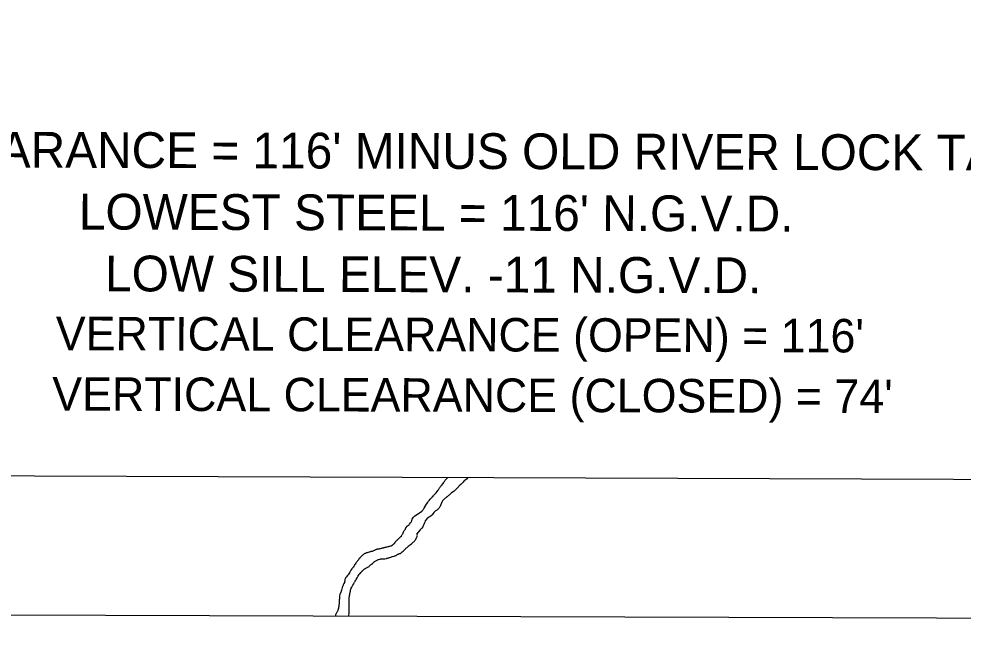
# Model space of a CAD drawing. Extents: x 3146026 to 3183936, y 897894 to 923344.
# Drawn here: x 3151849 to 3154671, y 903274 to 905151 of the extents above; entities that cross this region are included whole.
import ezdxf

# ---------------------------------------------------------------- set-up
doc = ezdxf.new("R2010")
doc.units = 0
for name, color, linetype in [('V-ANNO-SYMB', 7, 'Continuous'), ('V-GRID-FRAM', 7, 'Continuous'), ('V-TOPO-SHOR', 7, 'Continuous')]:
    doc.layers.add(name, color=color, linetype=linetype)

msp = doc.modelspace()

# ---------------------------------------------------------------- linework, layer by layer
at = {"layer": 'V-ANNO-SYMB'}
msp.add_lwpolyline([(3150260.2, 907341.2), (3165911.3, 907284.3), (3165898.4, 903734.3), (3150247.3, 903791.2)], close=True, dxfattribs=at)
at = {"layer": 'V-GRID-FRAM'}
msp.add_lwpolyline([(3150311.9, 921563.1), (3181637, 921462.9), (3181586.7, 903274.3), (3150245.8, 903374.5), (3150311.9, 921563.1)], dxfattribs=at)
at = {"layer": 'V-TOPO-SHOR'}
for points in [[(3153004.6, 903626.7), (3153005, 903628.2), (3153005.7, 903629.3), (3153005.9, 903630.4), (3153006.3, 903631.5), (3153009.8, 903635.4), (3153010.9, 903636), (3153014, 903638.4), (3153015.5, 903639.9), (3153016.8, 903641.6), (3153020.1, 903645.3), (3153020.5, 903646.6), (3153021.2, 903647.4), (3153023.2, 903651.5), (3153023.8, 903652.4), (3153024.9, 903656.1), (3153026.9, 903659.7), (3153028.4, 903661.9), (3153031.5, 903665.3), (3153032.6, 903666.2), (3153043.9, 903673.1), (3153045.2, 903674.1), (3153046.5, 903674.8), (3153053, 903680.4), (3153054.3, 903681.2), (3153056.5, 903683.6), (3153057.6, 903685.1), (3153058.2, 903686.6), (3153059.1, 903687.9), (3153060.2, 903689.2), (3153062.2, 903692), (3153062.6, 903693.1), (3153067.2, 903700.8), (3153068.5, 903702.4), (3153071.4, 903707.1), (3153072.4, 903708.4), (3153073.3, 903709.9), (3153074.4, 903711.2), (3153075.1, 903712.3), (3153078.1, 903715.9), (3153079.7, 903717.4), (3153082.3, 903720.5), (3153084.9, 903723), (3153086.9, 903725.6), (3153087.9, 903726.5), (3153089, 903727.8), (3153092.1, 903730.8), (3153093.2, 903731.7), (3153096, 903734.7), (3153099.1, 903739), (3153102.1, 903742.7), (3153103, 903743.9), (3153104.1, 903746.3), (3153106.3, 903749.6), (3153107.8, 903752.4), (3153109.6, 903754.3), (3153111.9, 903756.5), (3153117.2, 903763.1), (3153118.1, 903764.2), (3153118.7, 903765.5), (3153120.9, 903768.7), (3153123.5, 903773.1), (3153126.6, 903776.3), (3153128.3, 903777.6), (3153131.5, 903780.8)], [(3153190.7, 903780.5), (3153187, 903776.3), (3153182, 903771.8), (3153179.4, 903769.7), (3153177.2, 903767.1), (3153175.9, 903765.8), (3153169.6, 903760.2), (3153165.2, 903755.7), (3153164.3, 903754.4), (3153150, 903740.2), (3153146.9, 903737.8), (3153142.6, 903734.8), (3153141.5, 903733.7), (3153140.4, 903733.3), (3153139.5, 903732.2), (3153134.7, 903728.4), (3153133.2, 903726.9)], [(3153133.2, 903726.9), (3153129.1, 903723.4), (3153127.8, 903722.6), (3153124.7, 903720), (3153123, 903718.7), (3153119.1, 903715.3), (3153118, 903713.7), (3153115.6, 903711.2), (3153113.4, 903707.5), (3153112.9, 903706), (3153112.3, 903704.9), (3153109.4, 903697.3), (3153107.9, 903694.3), (3153106.4, 903691.9), (3153105.3, 903689.8), (3153103.9, 903688.7), (3153103.3, 903687.6), (3153102.2, 903686.6), (3153100.2, 903685.3), (3153097, 903682.3), (3153094.8, 903680.8), (3153089.8, 903675.8), (3153084.6, 903669.8), (3153082.2, 903667.4), (3153077.4, 903663.7), (3153076.3, 903663.3), (3153074.5, 903662.3), (3153073, 903661), (3153069.8, 903658.8), (3153068.5, 903657.5), (3153063.9, 903651.3), (3153062.1, 903647.8), (3153060.3, 903643.1), (3153059, 903640.3), (3153058.4, 903638.3), (3153057.9, 903636.4), (3153056.8, 903634.6), (3153056.2, 903633.1), (3153053.3, 903629.5), (3153048.5, 903624.7), (3153042.2, 903617.8), (3153038.5, 903612.9)], [(3153004.6, 903626.7), (3153001.6, 903624), (3153000.5, 903622), (3152999.6, 903620.6), (3152999, 903619.1), (3152998.1, 903617.9), (3152997.1, 903614.8), (3152995.3, 903611.5), (3152994.7, 903610.4), (3152993.8, 903608.8), (3152992.5, 903607.4), (3152991.7, 903605.2), (3152991.5, 903605), (3152990.6, 903604.1), (3152989.5, 903603.4), (3152988.6, 903602.5), (3152987.7, 903601.8), (3152986, 903600), (3152984.5, 903598.4), (3152983.4, 903597.8), (3152982.5, 903596.9), (3152981.9, 903596), (3152980.8, 903595.1), (3152980.1, 903594.2), (3152978.6, 903592.8), (3152977.5, 903591.7), (3152976.6, 903590.8), (3152975.3, 903589.2), (3152973.8, 903587.4), (3152972.9, 903586.3), (3152971.4, 903583.8), (3152970.3, 903582.7), (3152968.4, 903580.5), (3152966.2, 903578.9), (3152965.3, 903578.2), (3152963.8, 903577.3), (3152962.7, 903576.8), (3152961.4, 903576.1), (3152959.4, 903575.4), (3152956.7, 903574.5), (3152955, 903574.3), (3152953.9, 903574), (3152951.5, 903573.3), (3152948.8, 903572.6), (3152947.5, 903572.6), (3152945.5, 903572.1), (3152944.4, 903572.1), (3152943.3, 903571.8), (3152941.3, 903571.1), (3152940.2, 903570.9), (3152938.9, 903570.7), (3152937.5, 903570.2), (3152934.7, 903569.3), (3152933.1, 903569), (3152931.6, 903568.5), (3152928.7, 903567.8), (3152927.6, 903567.6), (3152926.5, 903567.4), (3152925.2, 903567.1), (3152923.9, 903566.9), (3152921.4, 903566.8), (3152920.3, 903566.6), (3152919, 903565.9), (3152917, 903565.4), (3152915.9, 903565), (3152914.8, 903564.3), (3152912.9, 903563.4), (3152911.8, 903562.9), (3152910.7, 903562.4), (3152909.3, 903561.8), (3152907.4, 903561.1), (3152904.7, 903560.1), (3152901.6, 903559.4), (3152900.3, 903558.9), (3152898.8, 903558.5), (3152896.6, 903558), (3152893.5, 903557.3), (3152892.1, 903556.8), (3152889.7, 903556.1), (3152888, 903555.4), (3152886.4, 903554.7), (3152885.3, 903554.3), (3152883.3, 903553.6), (3152881.1, 903552.4), (3152880.3, 903551.7), (3152879, 903550.6), (3152878.1, 903549.9), (3152876.3, 903548.8), (3152875.2, 903547.5), (3152873, 903545.9), (3152872, 903545), (3152871.1, 903543.8), (3152868.7, 903541.1), (3152867.8, 903540.2), (3152866.7, 903538.9), (3152865.7, 903537.6), (3152864.1, 903535.3), (3152861.3, 903531.9), (3152860, 903530.1), (3152858.9, 903528.8), (3152858.1, 903527.7)], [(3153015.8, 903577.5), (3153017.1, 903578.9), (3153018.2, 903579.8), (3153019.7, 903580.9), (3153022.3, 903583.2), (3153023.4, 903584.1), (3153024.5, 903585), (3153025.8, 903585.9), (3153028, 903587.7), (3153029.3, 903589.1), (3153031.3, 903590.7), (3153033, 903592.5), (3153033.9, 903593.6), (3153035.4, 903595.8), (3153036, 903597.2), (3153036.9, 903598.7), (3153037.7, 903600.7), (3153038.6, 903602.5), (3153039.7, 903605), (3153039.9, 903606.3), (3153040.5, 903608.1), (3153038.5, 903612.9)], [(3152863.5, 903487.5), (3152866.6, 903491.3), (3152867.6, 903492.9), (3152869.2, 903494.3), (3152871.3, 903497), (3152872, 903497.9), (3152873.1, 903499.4), (3152873.9, 903500.3), (3152874.8, 903501), (3152875.7, 903501.7), (3152877, 903502.6), (3152878.5, 903503.9), (3152880.5, 903505.7), (3152881.6, 903506.9), (3152882.9, 903507.8), (3152884, 903508.7), (3152885.1, 903509.4), (3152886.4, 903510.3), (3152888.6, 903511.4), (3152890.4, 903512.1), (3152891.9, 903513), (3152892.5, 903513.5), (3152892.5, 903513.5), (3152893, 903513.7), (3152894.5, 903514.4), (3152896.1, 903515.3), (3152897.6, 903516.9), (3152898.5, 903517.6), (3152899.6, 903518.5), (3152900.6, 903519.6), (3152901.5, 903520.3), (3152903.3, 903521.9), (3152905.7, 903523.7), (3152906.8, 903524.6), (3152908.1, 903525.7), (3152908.9, 903526.6), (3152910.3, 903528), (3152912.2, 903529.5), (3152913.5, 903530.2), (3152914.4, 903531.1), (3152916.4, 903532), (3152918.1, 903533), (3152919.7, 903533.9), (3152921, 903534.6), (3152922.1, 903535), (3152924.3, 903535.9), (3152928.5, 903537.1), (3152929.6, 903537.6), (3152931.6, 903537.8), (3152932.9, 903537.6), (3152934.9, 903537.9), (3152938.2, 903538.2), (3152940.4, 903537.8), (3152941.8, 903537.8), (3152943.1, 903538), (3152946.6, 903538.7), (3152947.7, 903539), (3152949, 903539.4), (3152950.6, 903539.7), (3152952.6, 903540.4), (3152955.7, 903541.1), (3152957, 903541.6), (3152960.5, 903542.5), (3152963.2, 903543.7), (3152964.3, 903544.1), (3152966.2, 903544.6), (3152969.8, 903545.8), (3152971.1, 903546.2), (3152972.6, 903546.7), (3152974.2, 903547.2), (3152975.7, 903547.4), (3152976.4, 903547.9), (3152977.5, 903548.8), (3152978.6, 903549.5), (3152980.5, 903550.8), (3152982.1, 903551.5), (3152983.4, 903552), (3152985.2, 903552.7), (3152986.3, 903553.4), (3152988.5, 903554.1), (3152989.6, 903554.3), (3152990.9, 903555.2), (3152991.7, 903556.1), (3152992.8, 903556.8), (3152993.9, 903557.5), (3152995.2, 903558.8), (3152998.1, 903561.1), (3152999, 903562), (3153000.3, 903563.6), (3153001.8, 903564.9), (3153002.7, 903565.8), (3153003.3, 903566.7), (3153004.8, 903568.1), (3153005.9, 903569.4), (3153007.5, 903570.5), (3153009.2, 903571.9), (3153010.5, 903573), (3153011.4, 903573.9), (3153012.9, 903575.3), (3153015.8, 903577.5)], [(3152858.1, 903527.7), (3152857.4, 903526.6), (3152856.1, 903524.5), (3152854.4, 903522.3), (3152852.7, 903519.8), (3152852.2, 903518.5), (3152850.9, 903516.7), (3152848.1, 903512.7), (3152847.5, 903511.6), (3152846.4, 903509.8), (3152845.8, 903508.9), (3152844.7, 903507.7), (3152841.6, 903504.4), (3152841.2, 903503.3), (3152840.3, 903501.9), (3152839.3, 903499.9), (3152838.8, 903498.8), (3152837.3, 903496.5), (3152835.2, 903493.4), (3152833.2, 903490.5), (3152831.7, 903488.5), (3152830.4, 903486.7), (3152828, 903484.4), (3152827.1, 903483.5), (3152825.8, 903481.3), (3152825.2, 903480.2), (3152824.5, 903478.6), (3152823.5, 903476.2), (3152823.1, 903474.8), (3152823.3, 903475), (3152823.1, 903473.3), (3152823.1, 903471.7), (3152822.9, 903469.5), (3152822.5, 903467.7), (3152820.8, 903464.6), (3152819.9, 903462.1), (3152818.9, 903460.4), (3152818, 903458.6), (3152817.2, 903456.1), (3152816.7, 903455), (3152816.1, 903453.9), (3152815.9, 903452.1), (3152814.9, 903448.3), (3152813.6, 903444.3), (3152813.2, 903443.2), (3152812.8, 903441.9), (3152812.1, 903439.9), (3152811, 903437.9), (3152809.4, 903433.4), (3152808.7, 903432.3), (3152808.3, 903431.2), (3152807.5, 903427.8), (3152807.3, 903424.9), (3152807.1, 903423.6), (3152807.1, 903422.3), (3152807.1, 903421.2), (3152807, 903417.8), (3152806.7, 903416.5), (3152806.8, 903414.7), (3152806.8, 903413.2), (3152806.6, 903409.6), (3152806.7, 903408.1), (3152806.3, 903405.9), (3152806.1, 903402.8), (3152805.7, 903400.8), (3152805.3, 903398.1), (3152805.3, 903397), (3152805.3, 903395), (3152804.9, 903393.2), (3152804.7, 903392.1), (3152804.5, 903390.3), (3152803.9, 903387.7), (3152802.8, 903384.8), (3152802.2, 903383.2), (3152801.3, 903381.6), (3152800.3, 903379.6), (3152799.6, 903378.3), (3152798.3, 903376.3), (3152796.8, 903372.9), (3152796, 903370.7), (3152795.1, 903368.9), (3152794.7, 903366.7), (3152794.6, 903366.4)], [(3152834.4, 903366.3), (3152834.5, 903366.8), (3152834.9, 903369.2), (3152835.6, 903370.5), (3152835.9, 903374.5), (3152836.4, 903375.9), (3152836.3, 903377.4), (3152836.5, 903378.1), (3152836.5, 903378.8), (3152836.3, 903380.7), (3152836.4, 903383.9), (3152836.2, 903386.1), (3152836.1, 903392.3), (3152836, 903394.7), (3152836, 903396.7), (3152836, 903399.8), (3152836.1, 903402.2), (3152835.9, 903404.7), (3152836, 903408.4), (3152836, 903409.5), (3152836, 903412), (3152836.2, 903413.8), (3152835.9, 903416), (3152835.9, 903418.2), (3152836.5, 903423.3), (3152836.9, 903425.1), (3152837.3, 903427.1), (3152837.5, 903428.4), (3152837.9, 903431.5), (3152838.5, 903435.1), (3152838.9, 903437.1), (3152839.3, 903438.6), (3152839.9, 903441.3), (3152840.5, 903444.4), (3152842.6, 903450.6), (3152843.9, 903453.5), (3152845.4, 903455.8), (3152846.3, 903457.3), (3152847.6, 903459.4), (3152850.2, 903463.2), (3152850.8, 903464.7), (3152851.5, 903465.8), (3152852.5, 903468.1), (3152853.4, 903469.6), (3152854.5, 903471.2), (3152856.2, 903474.6), (3152857.3, 903476.3), (3152857.9, 903477.2), (3152858.4, 903478.4), (3152860.1, 903481.5), (3152862, 903485.1), (3152862.9, 903486.6), (3152863.5, 903487.5)]]:
    msp.add_lwpolyline(points, dxfattribs=at)

# ---------------------------------------------------------------- texts
at = {"layer": 'V-ANNO-SYMB'}
for s, height, p in [("VERTICAL CLEARANCE = 116' MINUS OLD RIVER LOCK TAILBAY GAGE", 106.838, (3150773, 904709.4)), ("LOWEST STEEL = 116' N.G.V.D.", 106.838, (3152028.6, 904521.5)), ('LOW SILL ELEV. -11 N.G.V.D.', 106.838, (3152106.9, 904337)), ("VERTICAL CLEARANCE (OPEN) = 116'", 100, (3151959.7, 904161.2)), ("VERTICAL CLEARANCE (CLOSED) = 74'", 100, (3151949.1, 903980.6))]:
    msp.add_text(s, height=height, rotation=359.8334, dxfattribs=at).set_placement(p)

doc.saveas('drawing.dxf')
